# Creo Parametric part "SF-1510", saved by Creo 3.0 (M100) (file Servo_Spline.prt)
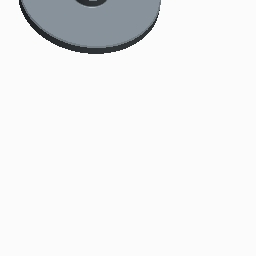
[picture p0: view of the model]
Units: Inch lbm Second (Pro/E Default); INCH, POUND, SECS
Materials in the file: AL6061, FE40, BRASS, SS, NYLON, STEEL

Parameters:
  DESCRIPTION = "FAB"
  PTC_COMMON_NAME = "sf-1510.prt"
  REV = "1"
  TITLE = "DRAWING TITLE"
  PTC_MATERIAL_NAME = "SS"
  MATL_METALS = "TBD"
  MATL_CAST = "TBD"
  MATL_SHT_METALS = "TBD"
  MATL_PLAST_INJ = "TBD"
  MATL_PLAST_MACH = "TBD"
  PLATING_METALS = "TBD"
  FINISH_1 = "TBD"
  FINISH_2 = "TBD"
  FINISH_3 = "TBD"
  FINISH_SPI_1 = "TBD"
  FINISH_SPI_2 = "TBD"
  FINISH_SPI_3 = "TBD"
  TEXT_1 = "TBD"
  TEXT_2 = "TBD"
  TEXT_3 = "TBD"
  COMPANY = "TBD"
  MODELED_BY = "TBD"
  RELEASE_STATUS = "PRELIMINARY"

Other parameters: MASS, DENSITY

Created from: 1000-STARTPART-REV2.PRT

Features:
  1. datum plane "RIGHT"
  2. datum plane "TOP"
  3. datum plane "FRONT"
  4. coordinate system
  5. extrusion "Extrude 1"
  6. extrusion "Extrude 2"
  7. extruded cut "Extrude 3"
  8. pattern "Pattern 1"
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
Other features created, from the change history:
  extrusion "Extrude 4"
  pattern "Pattern 1" (2 times)
  extrusion "Extrude 4 [2]"
  extrusion "Extrude 4 [3]"
  extrusion "Extrude 4 [4]"
  extrusion "Extrude 4 [5]"
  extrusion "Extrude 4 [6]"
  extrusion "Extrude 4 [7]"
  extrusion "Extrude 4 [8]"
  extrusion "Extrude 4 [9]"
  extrusion "Extrude 4 [10]"
  extrusion "Extrude 4 [11]"
  extrusion "Extrude 4 [12]"
  extrusion "Extrude 4 [13]"
  extrusion "Extrude 4 [14]"
  extrusion "Extrude 4 [15]"
  extrusion "Extrude 4 [16]"
  extrusion "Extrude 4 [17]"
  extrusion "Extrude 4 [18]"
  extrusion "Extrude 4 [19]"
  extrusion "Extrude 4 [20]"
  extrusion "Extrude 4 [21]"
  extrusion "Extrude 4 [22]"
  extrusion "Extrude 4 [23]"
  extrusion "Extrude 4 [24]"
  extruded cut "Extrude 4"
  extruded cut "Extrude 3 [2]"
  extruded cut "Extrude 3 [3]"
  extruded cut "Extrude 3 [4]"
  extruded cut "Extrude 3 [5]"
  extruded cut "Extrude 3 [6]"
  extruded cut "Extrude 3 [7]"
  extruded cut "Extrude 3 [8]"
  extruded cut "Extrude 3 [9]"
  extruded cut "Extrude 3 [10]"
  extruded cut "Extrude 3 [11]"
  extruded cut "Extrude 3 [12]"
  extruded cut "Extrude 3 [13]"
  extruded cut "Extrude 3 [14]"
  extruded cut "Extrude 3 [15]"
  extruded cut "Extrude 3 [16]"
  extruded cut "Extrude 3 [17]"
  extruded cut "Extrude 3 [18]"
  extruded cut "Extrude 3 [19]"
  extruded cut "Extrude 3 [20]"
  extruded cut "Extrude 3 [21]"
  extruded cut "Extrude 3 [22]"
  extruded cut "Extrude 3 [23]"
  extruded cut "Extrude 3 [24]"
  extruded cut "Extrude 4 [2]"
  extruded cut "Extrude 4 [3]"
  extruded cut "Extrude 4 [4]"
  extruded cut "Extrude 4 [5]"
  extruded cut "Extrude 4 [6]"
  extruded cut "Extrude 4 [7]"
  extruded cut "Extrude 4 [8]"
  extruded cut "Extrude 4 [9]"
  extruded cut "Extrude 4 [10]"
  extruded cut "Extrude 4 [11]"
  extruded cut "Extrude 4 [12]"
  extruded cut "Extrude 4 [13]"
  extruded cut "Extrude 4 [14]"
  extruded cut "Extrude 4 [15]"
  extruded cut "Extrude 4 [16]"
  extruded cut "Extrude 4 [17]"
  extruded cut "Extrude 4 [18]"
  extruded cut "Extrude 4 [19]"
  extruded cut "Extrude 4 [20]"
  extruded cut "Extrude 4 [21]"
  extruded cut "Extrude 4 [22]"
  extruded cut "Extrude 4 [23]"
  extruded cut "Extrude 4 [24]"
  extruded cut "Extrude 5"
  extruded cut "Extrude 6"
  chamfer "Chamfer 1"
  round "Round 1"
  revolve "Revolve 1"
  round "Round 2"
  group "LOCAL_GROUP_1"

Other named items: BASE, SPUD, SPLINE_ID, SPLINE, FASTENER_HOLE, FASTENER_CBORE, LOCAL_GROUP, LOCAL_GROUP_2, LOCAL_GROUP_3

Family table entries: GENERIC, SF-1510_000, SF-1510_000, SF-1510, value(d_val), value(i_val), SF-1510_001, SF-1510_001, SF-1510, SF-1510_002, SF-1510_002, SF-1510, SF-1510_003, SF-1510_003, SF-1510, d12, d23, p47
